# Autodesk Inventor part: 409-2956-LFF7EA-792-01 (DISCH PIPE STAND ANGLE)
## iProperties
Shininess: 64.0
Angle Display Precision: 2
Document Length Units: 11272
Document Angle Units: 11279
Document Time Units: 11290
Document Mass Units: 11286
Document Length Units Precision: 3
Document Angle Units Precision: 2
Compacted: True
Created: 2002-04
Part Number: 409-2956-LFF7EA-792-01 (DISCH PIPE STAND ANGLE)
Description: DISCHARGE PIPE STAND ANGLE
Document SubType Name: Modeling
Designer: S. Boerckel
Mass: 4388.16 g
Surface Area: 1830.64 cm^2
Volume: 559.001 cm^3
Density: 7.85 g/cm^3
Cost Center: 2 x 2 x 1/4 ANGLE
Material: ASTM A36
Engineer: S. Boerckel
Density: 0.0
Volumn: 0.0
Area: 0.0
PropertySet Name: Model Information
Control State: 0
Master: False
Checked Out: False
length: 36.468 in
SMR: =<COST CENTER> - <MATERIAL>
Author: S. Boerckel
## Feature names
1. Extrusion1
